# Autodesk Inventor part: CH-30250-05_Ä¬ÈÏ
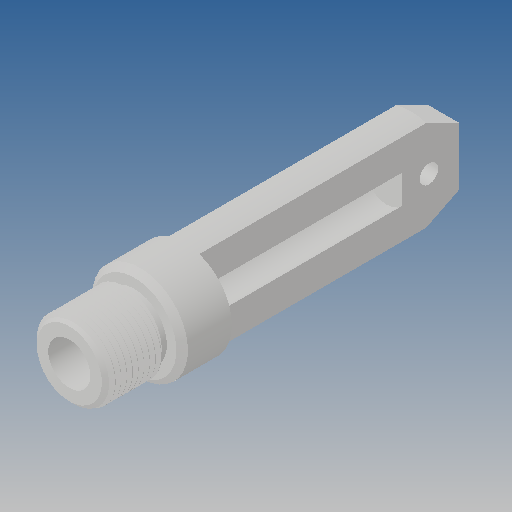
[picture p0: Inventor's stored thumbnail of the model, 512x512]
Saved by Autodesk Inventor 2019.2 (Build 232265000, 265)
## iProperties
Created: 2010-06
Part Number: CH-30250-05_Ä¬ÈÏ
Material: Ogólny
Document SubType Name: Modeling
Designer: CADENGINEERING4
Density: 1 g/cm^3
Appearance: Domyślna
Author: CADENGINEERING4
Revision Number: ÈÎºÎ
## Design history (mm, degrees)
feature "NONE"
node "Bryła1"
